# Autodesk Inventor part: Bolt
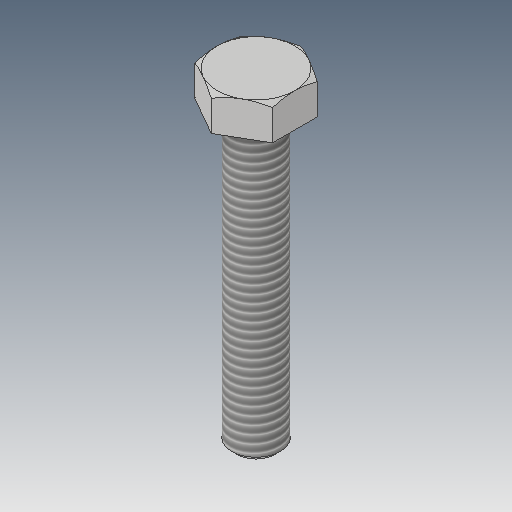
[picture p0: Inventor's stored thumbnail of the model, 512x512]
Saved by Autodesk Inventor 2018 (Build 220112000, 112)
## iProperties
Created: 2016-05
Part Number: Bolt
Material: Generic
Document SubType Name: Modeling
Designer: CADCIM
Density: 1 g/cm^3
Appearance: Default
Author: CADCIM
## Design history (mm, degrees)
sketch "Sketch1"
  geometry: L1 (3.604, -2.072)-(0.007, -4.157); L2 (0.007, -4.157)-(-3.596, -2.085); L3 (-3.596, -2.085)-(-3.604, 2.072); L4 (-3.604, 2.072)-(-0.007, 4.157); L5 (-0.007, 4.157)-(3.596, 2.085); L6 (3.596, 2.085)-(3.604, -2.072); 2 further points
  constraints: 12 end point, 1 coincident, 13 other
  dimensions: "d0" = 7.2 distance between parallel lines of L3 L6
extrude "Extrusion1" new body sketch "Sketch1" distance "d1" = 3.15; taper "d2" = 0 deg
sketch "Sketch2"
  geometry: C1 r 2.25 at (0, 0); 1 further point
  constraints: 1 centre point, 1 coincident
  dimensions: "d3" = 4.5 diameter of C1
extrude "Extrusion2" join sketch "Sketch2" distance "d4" = 27; taper "d5" = 0 deg
thread "Thread1" dims "d6" = 10, "d7" = 0
chamfer "Chamfer1" distance "d8" = 0.5; stored, may be unused: second distance "d9" = 2, angle "d10" = 45 deg
sketch "Sketch3"
  geometry: L1 (0.007, -4.157)-(3.604, -2.072) reference; C1 r 3.6 at (0, 0); 1 further point
  constraints: 1 centre point, 1 coincident, 1 tangent
extrude "Extrusion3" sketch "Sketch3" distance "d11" = 41; taper "d12" = 60 deg
body "Solid1"
